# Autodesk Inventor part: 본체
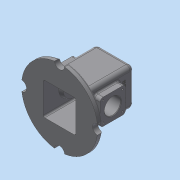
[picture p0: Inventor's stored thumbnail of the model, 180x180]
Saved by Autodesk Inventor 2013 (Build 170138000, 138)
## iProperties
Created: 2018-07
Part Number: 본체
Material: 일반
Document SubType Name: Modeling
Designer: Administrator
Density: 1 g/cm^3
Author: Administrator
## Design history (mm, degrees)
sketch "스케치1"
  geometry: L1 (37, -37)-(-37, -37); L2 (-37, -37)-(-37, 37); L3 (-37, 37)-(37, 37); L4 (37, 37)-(37, -37); L5 (37, -37)-(-37, 37); L6 (-37, -37)-(37, 37); 1 further point
  constraints: 12 end point, 2 midpoint, 2 parallel, 1 horizontal, 1 perpendicular
  dimensions: "d0" = 74 distance of L1.start L1.end; "d2" = 74 distance of L1.end L2.end
extrude "돌출1" new body sketch "스케치1" distance "d3" = 110; taper "d4" = 0 deg
fillet "모깎기1" dims "d5" = 8
fillet "모깎기2" dims "d6" = 8
feature "쉘1" dims "d7" = 5
node "작업 평면1"
sketch "스케치3"
  geometry: C1 r 17.5 at (0, 0); 1 further point
  constraints: 1 centre point, 1 coincident
  dimensions: "d9" = 35 diameter of C1
extrude "돌출2" join sketch "스케치3" stored distance "d11" = 110; taper "d12" = 0 deg
node "작업 평면2"
sketch "스케치4"
  geometry: L1 (-20, 20)-(20, 20); L2 (20, 20)-(20, -20); L3 (20, -20)-(-20, -20); L4 (-20, -20)-(-20, 20); L5 (-20, 20)-(20, -20); L6 (20, 20)-(-20, -20); C1 r 17.5 at (0, 0) reference; 1 further point
  constraints: 12 end point, 2 midpoint, 2 parallel, 1 horizontal, 1 perpendicular
  dimensions: "d14" = 40 distance of L2.end L3.end; "d15" = 40 distance of L1.end L2.end
extrude "돌출3" join sketch "스케치4" stored distance "d16" = 110; taper "d17" = 0 deg
fillet "모깎기3" dims "d18" = 3
fillet "모깎기4" dims "d19" = 3
hole "구멍1" diameter "d22" = 21; stored, may be unused: countersink angle "d26" = 90 deg, drill point angle "d28" = 118 deg; dims "d20" = 10, "d21" = 10, "d23" = 6, "d24" = 28, "d25" = 4, "d27" = 8
node "작업 평면3"
sketch "스케치5"
  geometry: L1 (-80, 25)-(-30, 25); L2 (-30, 25)-(-30, -25); L3 (-30, -25)-(-80, -25); L4 (-80, -25)-(-80, 25); L5 (-80, 25)-(-30, -25); L6 (-30, 25)-(-80, -25); L7 (0, 29)-(0, -29) reference; 3 further points
  constraints: 12 end point, 4 midpoint, 2 parallel, 1 horizontal, 1 horizontal alignment, 1 perpendicular
  dimensions: "d31" = 50 distance of L1.start L1.end; "d33" = 50 distance of L1.end L2.end; "d34" = 55 distance of point (0, 0) point (-55, 0)
extrude "돌출4" join sketch "스케치5" stored distance "d35" = 110; taper "d36" = 0 deg
sketch "스케치6"
  geometry: L1 (58, 0)-(0, 0) reference; C1 r 25 at (29, 55); 2 further points
  constraints: 1 centre point, 1 midpoint, 1 vertical alignment
  dimensions: "d37" = 50 diameter of C1; "d38" = 55 distance of point (29, 0) C1.centre
extrude "돌출5" join sketch "스케치6" distance "d39" = 7; taper "d40" = -20 deg
hole "구멍2" diameter "d43" = 32; stored, may be unused: countersink angle "d47" = 90 deg, drill point angle "d49" = 118 deg; dims "d41" = 10, "d42" = 10, "d44" = 6, "d45" = 28, "d46" = 4, "d48" = 8
fillet "모깎기5" dims "d50" = 6
fillet "모깎기6" dims "d51" = 3
sketch "스케치7"
  geometry: A1 r 6 centre (44, 38) between (50, 38) and (44, 44) reference; A2 r 6 centre (6, 38) between (6, 44) and (0, 38) reference; A3 r 6 centre (6, 0) between (0, 0) and (6, -6) reference; A4 r 6 centre (44, 0) between (44, -6) and (50, 0) reference; 5 further points
  constraints: 4 coincident
hole "구멍3" sketch "스케치7" at (6, 38), (44, 38), (6, 0), (44, 0) diameter "d52" = 3.242; stored, may be unused: countersink angle "d56" = 90 deg, drill point angle "d58" = 118 deg; dims "d53" = 8, "d54" = 28, "d55" = 4, "d57" = 10
chamfer "모따기1" distance "d59" = 1; stored, may be unused: second distance "d60" = 2, angle "d61" = 45 deg
sketch "스케치8"
  geometry: L1 (-32, -29)-(-32, 29) reference; L2 (-29, 32)-(29, 32) reference; L3 (32, 29)-(32, -29) reference; L4 (29, -32)-(-29, -32) reference; C1 r 75 at (0, 0); A1 r 3 centre (-29, -29) between (-32, -29) and (-29, -32) reference; A2 r 3 centre (-29, 29) between (-29, 32) and (-32, 29) reference; A3 r 3 centre (29, 29) between (32, 29) and (29, 32) reference; A4 r 3 centre (29, -29) between (29, -32) and (32, -29) reference; 1 further point
  constraints: 1 centre point, 1 coincident
  dimensions: "d62" = 150 diameter of C1
extrude "돌출6" join sketch "스케치8" distance "d63" = 10; taper "d64" = 0 deg
sketch "스케치9"
  geometry: C1 r 10 at (0, 75); C2 r 10 at (-75, 0); C3 r 10 at (0, -75); C4 r 10 at (75, 0); 1 further point
  constraints: 4 centre point, 2 vertical alignment, 10 other
  dimensions: "d65" = 20 diameter of C1; "d68" = 360 deg dimension on point (0, 0) C1.centre (derived)
extrude "돌출7" cut sketch "스케치9" stored distance "d70" = 0; taper "d71" = 0 deg
fillet "모깎기7" dims "d73" = 3
sketch "스케치10"
  geometry: L1 (66, -89)-(66, 0) reference; L2 (46.5, 18)-(11.5, 18) reference; 2 further points
  constraints: 1 other
  dimensions: "d74" = 37 distance from line of L1 point (29, -12); "d75" = 30 distance from line of L2 point (29, -12)
feature "엠보싱1" sketch "스케치10" dims "d0" = 74, "d2" = 74, "d76" = 0.5, "d77" = 0
node "솔리드1"
mirror "대칭1"
mirror "대칭2"
other parameters: "d13" = -3
